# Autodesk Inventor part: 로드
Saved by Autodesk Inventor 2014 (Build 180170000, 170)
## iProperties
Created: 2026-03
Part Number: 로드
Material: 강철, 탄소
Document SubType Name: Modeling
Designer: dg
Density: 7.87 g/cm^3
Appearance: 반연마
Mass: 398.288 g
Surface Area: 146.117 cm^2
Volume: 50.6084 cm^3
Author: jhkim
Creation Date: 2025-06-27
Sending System: Autodesk Inventor 2026
Preprocessor: ST-DEVELOPER v20.1
Author: dg
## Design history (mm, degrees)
node "로드1"
node "솔리드1"
node "기준1"
